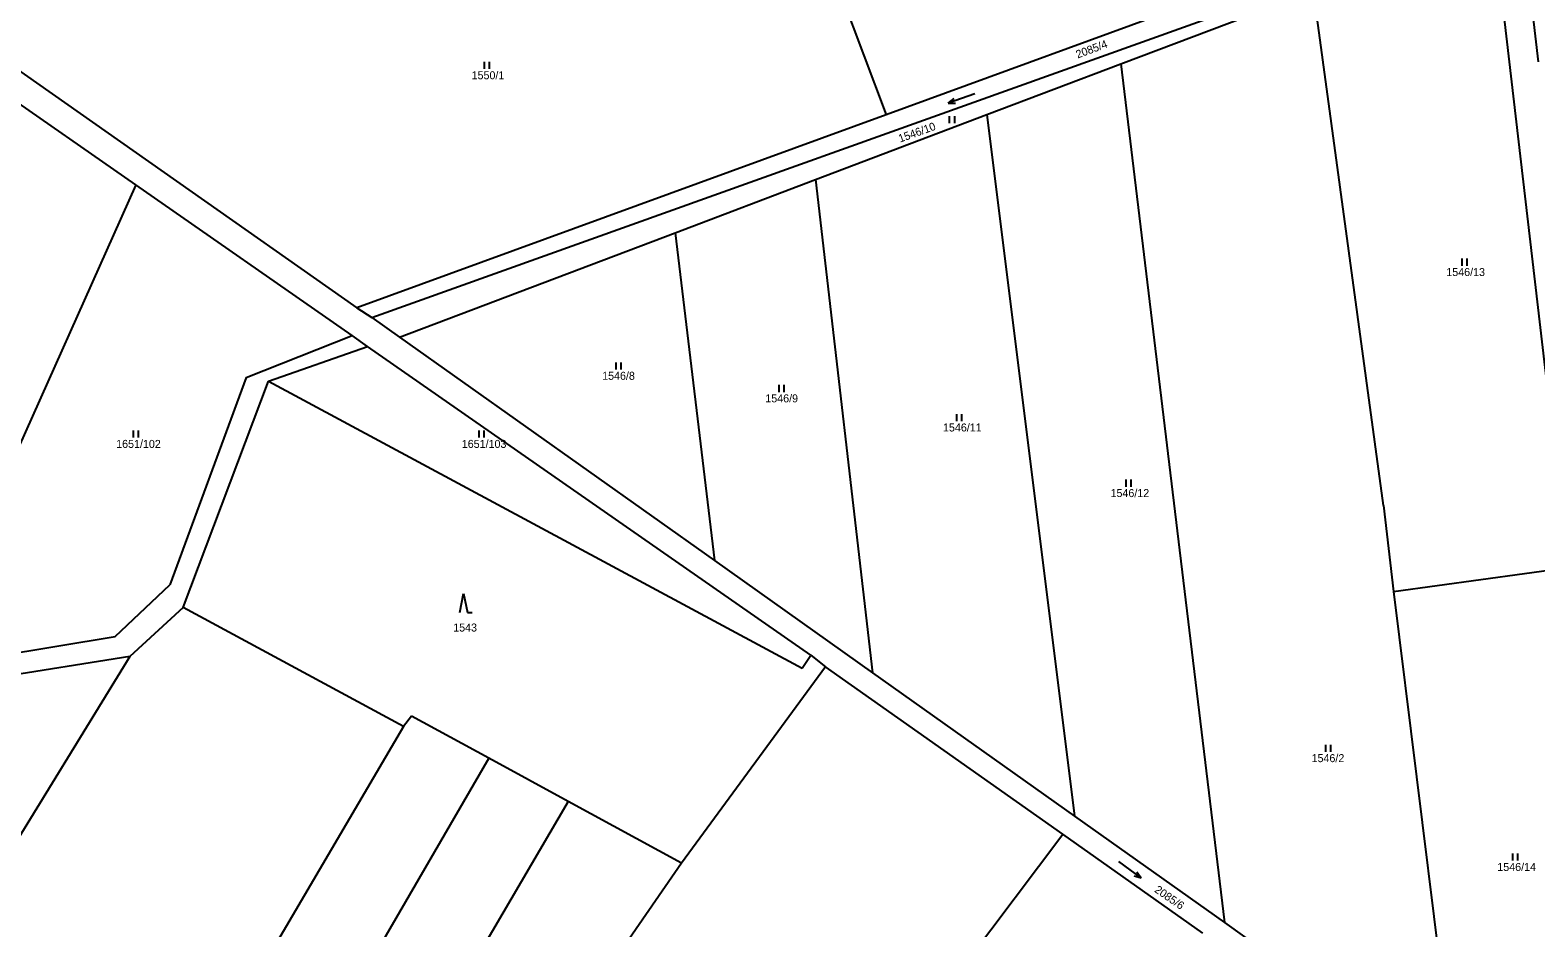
# Model space of a CAD drawing. Extents: x -795483 to -789093, y -1112258 to -1108741.
# Drawn here: x -792849.3 to -792529.4, y -1111364.2 to -1111173.4 of the extents above; entities that cross this region are included whole.
import ezdxf

# ---------------------------------------------------------------- set-up
doc = ezdxf.new("R2010")
doc.units = 0
for name, color, linetype in [('Vrstva 1', 7, 'Continuous'), ('Vrstva 10', 7, 'Continuous'), ('Vrstva 14', 7, 'Continuous'), ('Vrstva 23', 7, 'Continuous')]:
    doc.layers.add(name, color=color, linetype=linetype)

msp = doc.modelspace()

# ---------------------------------------------------------------- linework, layer by layer
at = {"layer": 'Vrstva 1'}
for p, q in [((-792687.86, -1111136.86), (-792667.43, -1111191.37)), ((-792539.2, -1111144.55), (-792667.43, -1111191.37)), ((-792528.81, -1111180.11), (-792532.58, -1111147.1)), ((-792776.7, -1111234.46), (-792538.65, -1111149.27)), ((-792538.49, -1111150.63), (-792522.49, -1111287.63)), ((-792617.54, -1111180.58), (-792576.63, -1111165.08)), ((-792561.77, -1111274.42), (-792576.63, -1111165.08)), ((-792862.84, -1111174.18), (-792779.93, -1111232.45)), ((-792646.01, -1111191.36), (-792617.54, -1111180.58)), ((-792617.54, -1111180.58), (-792605.58, -1111279.82)), ((-792826.86, -1111206.31), (-792858.59, -1111184.19)), ((-792667.43, -1111191.37), (-792779.93, -1111232.45)), ((-792682.42, -1111205.16), (-792646.01, -1111191.36)), ((-792646.01, -1111191.36), (-792627.37, -1111340.5)), ((-792712.29, -1111216.48), (-792682.42, -1111205.16)), ((-792682.42, -1111205.16), (-792670.29, -1111310.02)), ((-792826.86, -1111206.31), (-792872.85, -1111309.09)), ((-792780.91, -1111238.33), (-792826.86, -1111206.31)), ((-792770.8, -1111238.65), (-792712.29, -1111216.48)), ((-792712.29, -1111216.48), (-792703.9, -1111286.15)), ((-792779.93, -1111232.45), (-792776.7, -1111234.46)), ((-792776.7, -1111234.46), (-792770.8, -1111238.65)), ((-792803.4, -1111247.24), (-792780.91, -1111238.33)), ((-792777.64, -1111240.61), (-792780.91, -1111238.33)), ((-792770.8, -1111238.65), (-792703.9, -1111286.15)), ((-792798.67, -1111248), (-792777.64, -1111240.61)), ((-792683.4, -1111306.29), (-792777.64, -1111240.61)), ((-792803.4, -1111247.24), (-792819.61, -1111291.3)), ((-792816.81, -1111296.11), (-792798.67, -1111248)), ((-792798.67, -1111248), (-792685.24, -1111308.99)), ((-792561.77, -1111274.42), (-792559.59, -1111292.73)), ((-792605.58, -1111279.82), (-792595.54, -1111363.1)), ((-792703.9, -1111286.15), (-792670.29, -1111310.02)), ((-792559.59, -1111292.73), (-792522.49, -1111287.63)), ((-792831.22, -1111302.3), (-792819.61, -1111291.3)), ((-792559.59, -1111292.73), (-792547.15, -1111393.33)), ((-792816.81, -1111296.11), (-792828.17, -1111306.54)), ((-792769.97, -1111321.4), (-792816.81, -1111296.11)), ((-792872.85, -1111309.09), (-792831.22, -1111302.3)), ((-792828.17, -1111306.54), (-792903.07, -1111428.71)), ((-792828.17, -1111306.54), (-792866.37, -1111312.65)), ((-792685.24, -1111308.99), (-792683.4, -1111306.29)), ((-792683.4, -1111306.29), (-792680.34, -1111308.76)), ((-792680.34, -1111308.76), (-792710.93, -1111350.46)), ((-792629.9, -1111344.34), (-792680.34, -1111308.76)), ((-792670.29, -1111310.02), (-792627.37, -1111340.5)), ((-792768.27, -1111319.22), (-792769.97, -1111321.4)), ((-792751.85, -1111328.17), (-792768.27, -1111319.22)), ((-792769.97, -1111321.4), (-792840.16, -1111440.93)), ((-792751.85, -1111328.17), (-792816.06, -1111438.75)), ((-792734.98, -1111337.36), (-792751.85, -1111328.17)), ((-792734.98, -1111337.36), (-792791.96, -1111434.62)), ((-792710.93, -1111350.46), (-792734.98, -1111337.36)), ((-792627.37, -1111340.5), (-792595.54, -1111363.1)), ((-792693.59, -1111428.94), (-792629.9, -1111344.34)), ((-792600.1, -1111365.36), (-792629.9, -1111344.34)), ((-792710.93, -1111350.46), (-792736.76, -1111387.99)), ((-792595.54, -1111363.1), (-792551.86, -1111394.12))]:
    msp.add_line(p, q, dxfattribs=at)
at = {"layer": 'Vrstva 10'}
msp.add_arc((-130932.1, -1036421.88), 665802.44, 186.43100278, 186.47566111, dxfattribs=at)
at = {"layer": 'Vrstva 23'}
for p, q in [((-792752.78, -1111181.64), (-792752.78, -1111180.14)), ((-792751.78, -1111180.14), (-792751.78, -1111181.64)), ((-792648.55, -1111186.96), (-792654.23, -1111188.9)), ((-792654.23, -1111188.9), (-792652.97, -1111187.94)), ((-792654.23, -1111188.9), (-792652.65, -1111188.89)), ((-792653.93, -1111193.2), (-792653.93, -1111191.7)), ((-792652.93, -1111191.7), (-792652.93, -1111193.2)), ((-792545.04, -1111223.47), (-792545.04, -1111221.97)), ((-792544.04, -1111221.97), (-792544.04, -1111223.47)), ((-792724.78, -1111245.52), (-792724.78, -1111244.02)), ((-792723.78, -1111244.02), (-792723.78, -1111245.52)), ((-792690.13, -1111250.32), (-792690.13, -1111248.82)), ((-792689.13, -1111248.82), (-792689.13, -1111250.32)), ((-792652.38, -1111256.51), (-792652.38, -1111255.01)), ((-792651.38, -1111255.01), (-792651.38, -1111256.51)), ((-792827.38, -1111260), (-792827.38, -1111258.5)), ((-792826.38, -1111258.5), (-792826.38, -1111260)), ((-792753.93, -1111260), (-792753.93, -1111258.5)), ((-792752.93, -1111258.5), (-792752.93, -1111260)), ((-792616.4, -1111270.45), (-792616.4, -1111268.95)), ((-792615.4, -1111268.95), (-792615.4, -1111270.45)), ((-792758.01, -1111297.16), (-792757.21, -1111293.16)), ((-792757.21, -1111293.16), (-792756.41, -1111297.16)), ((-792756.41, -1111297.16), (-792755.41, -1111297.16)), ((-792573.99, -1111326.8), (-792573.99, -1111325.3)), ((-792572.99, -1111325.3), (-792572.99, -1111326.8)), ((-792534.28, -1111349.93), (-792534.28, -1111348.43)), ((-792533.28, -1111348.43), (-792533.28, -1111349.93)), ((-792618.06, -1111350.13), (-792613.22, -1111353.69)), ((-792613.22, -1111353.69), (-792614.13, -1111352.39)), ((-792613.22, -1111353.69), (-792614.73, -1111353.2))]:
    msp.add_line(p, q, dxfattribs=at)

# ---------------------------------------------------------------- texts
at = {"layer": 'Vrstva 14'}
for s, rotation, p in [('2085/4', 20.4757, (-792626.74, -1111179.44)), ('1546/10', 19.9012, (-792664.46, -1111197.31)), ('2085/6', 325.3262, (-792610.55, -1111356.48))]:
    msp.add_text(s, height=1.7, rotation=rotation, dxfattribs=at).set_placement(p)
for s, p in [('1550/1', (-792755.51, -1111183.84)), ('1546/13', (-792548.39, -1111225.67)), ('1546/8', (-792727.77, -1111247.72)), ('1546/9', (-792693.1, -1111252.52)), ('1546/11', (-792655.34, -1111258.71)), ('1651/102', (-792831.04, -1111262.2)), ('1651/103', (-792757.6, -1111262.2)), ('1546/12', (-792619.74, -1111272.65)), ('1543', (-792759.42, -1111301.23)), ('1546/2', (-792577.02, -1111329)), ('1546/14', (-792537.55, -1111352.13))]:
    msp.add_text(s, height=1.7, dxfattribs=at).set_placement(p)

doc.saveas('drawing.dxf')
